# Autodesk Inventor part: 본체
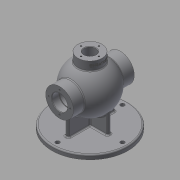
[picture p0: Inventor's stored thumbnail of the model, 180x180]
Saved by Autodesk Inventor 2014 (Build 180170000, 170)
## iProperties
Created: 2020-08
Part Number: 본체
Material: Generic
Document SubType Name: Modeling
Designer: kh
Density: 1 g/cm^3
Appearance: Default
Author: kh
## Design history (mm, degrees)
sketch "Sketch1"
  geometry: C1 r 85 at (0, 0); 1 further point
  constraints: 1 centre point, 1 coincident
  dimensions: "d0" = 170 diameter of C1
extrude "Extrusion1" new body sketch "Sketch1" distance "d1" = 10; taper "d2" = 0 deg
sketch "Sketch2"
  geometry: L1 (-87.595, 85)-(79.188, 85); L2 (-68, 102.5)-(-52, 102.5); L3 (-52, 102.5)-(-52, 103.5); L4 (-52, 103.5)-(-50.25, 103.5); L5 (-50.25, 103.5)-(-50.25, 102.5); L6 (-50.25, 102.5)-(-39.278, 102.5); L7 (68, 102.5)-(39.278, 102.5); L8 (-68, 102.5)-(-68, 116); L9 (-68, 116)-(-42.988, 116); L10 (68, 102.5)-(68, 116); L11 (68, 116)-(42.988, 116); L12 (0, 0)-(0, 38.889); L13 (-85, 0)-(85, 0) reference; A1 r 43 centre (0, 85) between (39.278, 102.5) and (-39.278, 102.5); A2 r 53 centre (0, 85) between (42.988, 116) and (-42.988, 116)
  constraints: 24 end point, 6 perpendicular, 4 point on circle, 3 parallel, 2 centre point, 2 collinear, 2 point on line, 1 horizontal, 1 other
  dimensions: "d3" = 35 diameter of L2 L1; "d4" = 37 diameter of L4 L1; "d5" = 35 diameter of L6 L1; "d6" = 35 diameter of L7 L1; "d7" = 62 diameter of L11 L1; "d8" = 62 diameter of L9 L1; "d9" = 53 radius of A2; "d10" = 43 radius of A1; "d11" = 85 distance from line of L13 L1.end; "d12" = 136 distance between parallel lines of L10 L8; "d13" = 1.75 distance of L3.end L4.end; "d14" = 16 distance of L2.start L2.end
revolve "Revolution1" sketch "Sketch2" stored, may be unused: angle "d15" = 90 deg
sketch "Sketch3"
  geometry: L1 (-43, -4)-(43, -4); L2 (43, -4)-(43, 4); L3 (43, 4)-(-43, 4); L4 (-43, 4)-(-43, -4); L5 (-43, -4)-(43, 4); L6 (43, -4)-(-43, 4); L7 (-4, -52)-(4, -52); L8 (4, -52)-(4, 52); L9 (4, 52)-(-4, 52); L10 (-4, 52)-(-4, -52); L11 (-4, -52)-(4, 52); L12 (4, -52)-(-4, 52); 1 further point
  constraints: 24 end point, 4 midpoint, 4 parallel, 2 horizontal, 2 perpendicular
  dimensions: "d16" = 86 distance of L2.end L3.end; "d17" = 8 distance of L1.end L2.end; "d18" = 8 distance of L8.end L9.end; "d19" = 104 distance of L7.end L8.end
extrude "Extrusion2" join sketch "Sketch3" stored distance "d20" = 10; taper "d21" = 0 deg
workplane "Work Plane1"
sketch "Sketch4"
  geometry: C1 r 27 at (0, 0); 1 further point
  constraints: 1 centre point, 1 coincident
  dimensions: "d23" = 54 diameter of C1
extrude "Extrusion3" join sketch "Sketch4" stored distance "d24" = 10; taper "d25" = 0 deg
hole "Hole1" diameter "d28" = 26; stored, may be unused: countersink angle "d32" = 90 deg, drill point angle "d34" = 118 deg; dims "d26" = 10, "d27" = 10, "d29" = 6, "d30" = 4, "d31" = 2, "d33" = 8
workplane "Work Plane2"
sketch "Sketch6"
  geometry: L1 (-20.739, -5.998)-(20.739, -5.998); L2 (20.739, -5.998)-(20.739, -12.002); L3 (20.739, -12.002)-(-20.739, -12.002); L4 (-20.739, -12.002)-(-20.739, -5.998); L5 (-20.739, -5.998)-(20.739, -12.002); L6 (-27, 0)-(27, 0) reference; L7 (-27, 0)-(-27, -19.393) reference; 2 further points
  constraints: 2 end point, 1 midpoint, 2 other
  dimensions: "d35" = 9 distance from line of point (0, -9) L6; "d36" = 27 distance from line of L7 point (0, -9)
emboss "Emboss1" sketch "Sketch6" dims "d1" = 10, "d2" = 0, "d37" = 0.5, "d38" = 0
chamfer "Chamfer1" distance "d39" = 1; stored, may be unused: second distance "d40" = 2, angle "d41" = 45 deg
fillet "Fillet1" dims "d42" = 3
fillet "Fillet2" dims "d43" = 3
sketch "Sketch7" dims "d44" = 145
  geometry: L1 (0, 0)-(0, 72.5); 2 further points
  constraints: 2 coincident, 2 end point, 1 vertical, 1 vertical alignment, 2 other
hole "Hole2" sketch "Sketch7" at (0, 72.5) diameter "d45" = 9; stored, may be unused: countersink angle "d49" = 90 deg, drill point angle "d51" = 118 deg; dims "d46" = 6, "d47" = 4, "d48" = 2, "d50" = 8
pattern_circular "Circular Pattern1" dims angle "d53" = 360 deg
fillet "Fillet3" dims "d55" = 3
sketch "Sketch8" dims "d56" = 48
  geometry: L1 (0, 0)-(0, 24); C1 r 31 at (0, 0) reference; 2 further points
  constraints: 2 coincident, 2 end point, 1 vertical, 1 vertical alignment, 2 other
hole "Hole3" sketch "Sketch8" at (0, 24) diameter "d57" = 3.242; stored, may be unused: countersink angle "d61" = 90 deg, drill point angle "d63" = 118 deg; dims "d58" = 12, "d59" = 4, "d60" = 2, "d62" = 15
pattern_circular "Circular Pattern2" dims angle "d65" = 360 deg
sketch "Sketch9" dims "d67" = 48
  geometry: L1 (0, 0)-(0, -24); C1 r 31 at (0, 0) reference; 2 further points
  constraints: 2 coincident, 2 end point, 1 vertical, 1 vertical alignment, 2 other
hole "Hole4" sketch "Sketch9" at (0, -24) diameter "d68" = 3.242; stored, may be unused: countersink angle "d72" = 90 deg, drill point angle "d74" = 118 deg; dims "d69" = 12, "d70" = 4, "d71" = 2, "d73" = 15
pattern_circular "Circular Pattern3" dims angle "d76" = 360 deg
sketch "Sketch10" dims "d78" = 40
  geometry: L1 (0, 0)-(0, 20); C1 r 27 at (0, 0) reference; 2 further points
  constraints: 2 coincident, 2 end point, 1 vertical, 1 vertical alignment, 2 other
hole "Hole5" sketch "Sketch10" at (0, 20) diameter "d79" = 3.242; stored, may be unused: countersink angle "d83" = 90 deg, drill point angle "d85" = 118 deg; dims "d80" = 12, "d81" = 4, "d82" = 2, "d84" = 15
pattern_circular "Circular Pattern4" dims angle "d87" = 360 deg
fillet "Fillet4" dims "d89" = 3
body "Solid1"
